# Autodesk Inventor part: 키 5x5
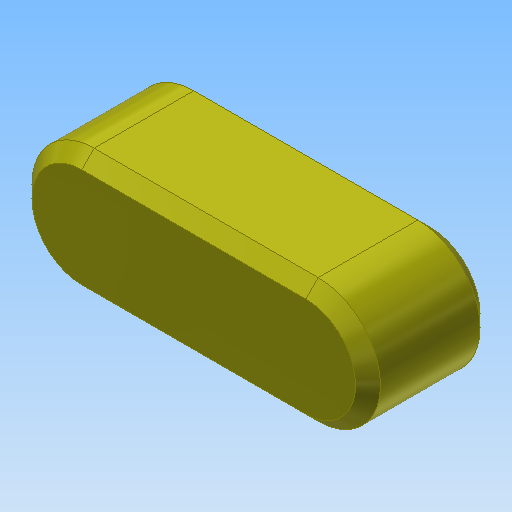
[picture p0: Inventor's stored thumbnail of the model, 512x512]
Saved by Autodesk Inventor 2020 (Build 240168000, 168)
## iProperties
Created: 2016-04
Part Number: 키 5x5
Document SubType Name: Modeling
Designer: mdu
Density: 7.86 g/cm^3
Mass: 2.54015 g
Surface Area: 2.9781 cm^2
Volume: 0.323175 cm^3
Material: 강철, 연강
Appearance: 노란색
Author: mdu
Revision Number: 1
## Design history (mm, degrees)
sketch "스케치1"
  geometry: L1 (-4.5, -2.5)-(4.5, -2.5); L2 (4.5, 2.5)-(-4.5, 2.5); A1 r 2.5 centre (4.5, 0) between (4.5, -2.5) and (4.5, 2.5); A2 r 2.5 centre (-4.5, 0) between (-4.5, 2.5) and (-4.5, -2.5); 2 further points
  constraints: 4 end point, 4 point on circle, 4 tangent, 2 centre point, 1 horizontal, 1 horizontal alignment, 1 midpoint, 1 parallel, 1 vertical alignment
  dimensions: "d0" = 5 distance between parallel lines of L1 L2; "d1" = 14 dimension on A1 A2
extrude "돌출1" new body sketch "스케치1" stored distance "d2" = 5; taper "d3" = 0 deg
chamfer "모따기1" distance "d4" = 0.5; stored, may be unused: second distance "d5" = 2, angle "d6" = 45 deg
node "솔리드1"
